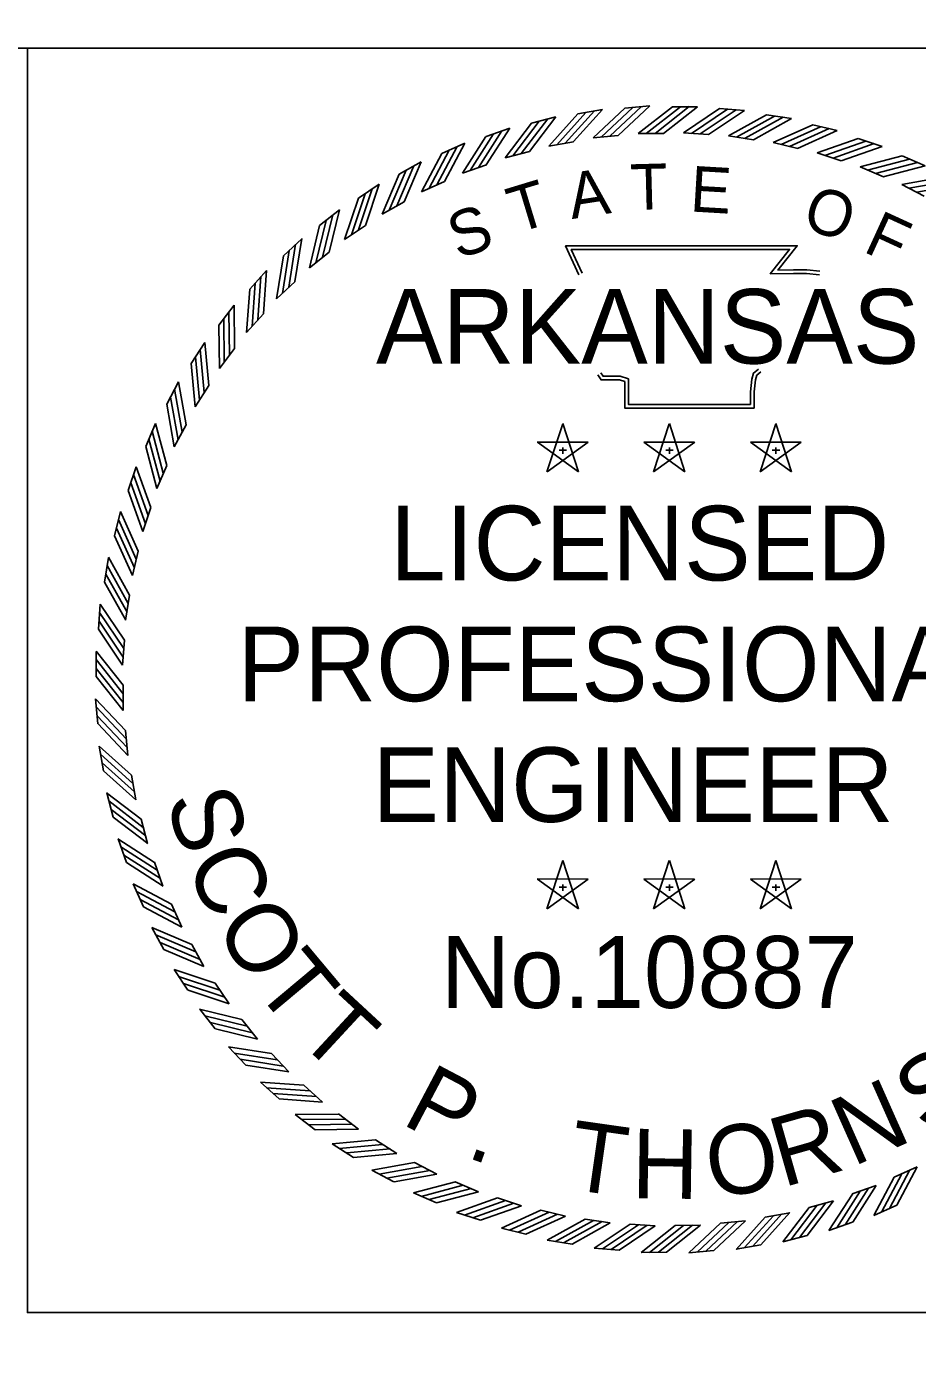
# Model space of a CAD drawing. Extents: x 0 to 1228740, y 0 to 152440.
# Drawn here: x 30.665 to 32.593, y 17.304 to 20.19 of the extents above; entities that cross this region are included whole.
import ezdxf

# ---------------------------------------------------------------- set-up
doc = ezdxf.new("R2010")
doc.units = 0
for name, color, linetype in [('R_Border', 7, 'Continuous'), ('R_No Plot', 7, 'Continuous'), ('STAMP_PP', 7, 'Continuous')]:
    doc.layers.add(name, color=color, linetype=linetype)

msp = doc.modelspace()

# ---------------------------------------------------------------- linework, layer by layer
at = {"layer": 'R_Border'}
msp.add_line((29.1131, 20.1432), (33.4231, 20.1432), dxfattribs=at)
at = {"layer": 'R_No Plot'}
for points in [[(33.4231, 17.4052), (33.4231, 0.5768), (1.516, 0.5768), (1.516, 21.4232), (20.2672, 21.4232), (20.2672, 20.4352), (28.7566, 20.4351), (28.7566, 20.0873), (29.1132, 20.0873), (29.1131, 20.1432), (30.6665, 20.1432)], [(30.6665, 20.1432), (30.6665, 17.4052), (33.4231, 17.4052)]]:
    msp.add_lwpolyline(points, dxfattribs=at)
msp.add_lwpolyline([(20.2672, 21.4232), (1.516, 21.4232), (1.516, 10.8708), (33.4231, 10.8708), (33.4231, 17.4052), (30.6665, 17.4052), (30.6665, 20.1432), (29.1132, 20.1432), (29.1132, 20.0873), (28.7566, 20.0873), (28.7566, 20.4351), (20.2672, 20.4351)], close=True, dxfattribs=at)
at = {"layer": 'STAMP_PP'}
for p, q in [((31.8584, 20.0015), (31.912, 20.0109)), ((31.9602, 20.0137), (32.0144, 20.0186)), ((32.0633, 20.0167), (32.1177, 20.0167)), ((32.1652, 20.0126), (32.2194, 20.0086)), ((31.7579, 19.981), (31.8105, 19.9948)), ((32.2669, 19.9994), (32.3206, 19.9909)), ((32.3671, 19.9778), (32.42, 19.965)), ((31.6595, 19.9522), (31.7108, 19.9703)), ((31.8916, 19.9492), (31.9459, 19.9542)), ((31.989, 19.9588), (32.0435, 19.9588)), ((32.0869, 19.9603), (32.1413, 19.9563)), ((32.1845, 19.9538), (32.2384, 19.9453)), ((32.4653, 19.9481), (32.5169, 19.9309)), ((31.5637, 19.9154), (31.6134, 19.9377)), ((31.7008, 19.9061), (31.7536, 19.9199)), ((31.7953, 19.9316), (31.849, 19.941)), ((32.2813, 19.9392), (32.3343, 19.9263)), ((32.3766, 19.9166), (32.4283, 19.8994)), ((31.4714, 19.8708), (31.519, 19.8972)), ((31.6088, 19.8729), (31.6602, 19.891)), ((32.5606, 19.9103), (32.6107, 19.8889)), ((32.4696, 19.8863), (32.5198, 19.8648)), ((31.383, 19.8188), (31.4283, 19.849)), ((31.5198, 19.8321), (31.5695, 19.8545)), ((32.5598, 19.8484), (32.608, 19.8229)), ((31.4344, 19.7842), (31.4821, 19.8106)), ((31.2992, 19.7596), (31.3419, 19.7934)), ((31.3533, 19.7294), (31.3987, 19.7597)), ((31.2206, 19.6937), (31.2603, 19.7309)), ((31.277, 19.6681), (31.3198, 19.702)), ((31.1477, 19.6216), (31.1842, 19.6619)), ((31.2061, 19.6007), (31.2459, 19.638)), ((31.0811, 19.5437), (31.1141, 19.5869)), ((31.1409, 19.5277), (31.1775, 19.5681)), ((31.021, 19.4605), (31.0504, 19.5063)), ((31.082, 19.4495), (31.1151, 19.4928)), ((30.9681, 19.3727), (30.9935, 19.4207)), ((31.0298, 19.3667), (31.0592, 19.4127)), ((30.9226, 19.2807), (30.944, 19.3308)), ((30.9845, 19.28), (31.01, 19.3281)), ((31.8255, 19.3302), (31.7915, 19.2258)), ((31.8594, 19.2258), (31.8256, 19.3303)), ((32.0563, 19.3302), (32.0222, 19.2258)), ((32.0902, 19.2258), (32.0564, 19.3303)), ((32.2871, 19.3302), (32.253, 19.2258)), ((32.321, 19.2258), (32.2871, 19.3303)), ((31.8804, 19.2904), (31.7705, 19.2905)), ((31.7706, 19.2904), (31.8594, 19.2257)), ((31.7916, 19.2258), (31.8805, 19.2903)), ((32.1112, 19.2904), (32.0013, 19.2905)), ((32.0014, 19.2904), (32.0902, 19.2257)), ((32.0224, 19.2258), (32.1113, 19.2903)), ((32.3419, 19.2904), (32.2321, 19.2905)), ((32.2322, 19.2904), (32.321, 19.2257)), ((32.2532, 19.2258), (32.3421, 19.2903)), ((31.8177, 19.2728), (31.834, 19.2728)), ((31.8256, 19.2787), (31.8256, 19.2649)), ((32.0485, 19.2728), (32.0648, 19.2728)), ((32.0564, 19.2787), (32.0564, 19.2649)), ((32.2793, 19.2728), (32.2956, 19.2728)), ((32.2872, 19.2787), (32.2872, 19.2649)), ((30.8848, 19.1854), (30.902, 19.237)), ((30.9466, 19.1897), (30.9681, 19.2399)), ((30.855, 19.0873), (30.8679, 19.1401)), ((30.9163, 19.0967), (30.9335, 19.1484)), ((30.8937, 19.0014), (30.9066, 19.0544)), ((30.8335, 18.987), (30.8419, 19.0407)), ((30.8203, 18.8853), (30.8243, 18.9395)), ((30.8791, 18.9046), (30.8876, 18.9585)), ((30.8726, 18.807), (30.8766, 18.8614)), ((30.8155, 18.7828), (30.815, 18.8372)), ((30.8741, 18.7091), (30.8736, 18.7637)), ((30.8192, 18.6803), (30.8142, 18.7345)), ((30.8837, 18.6117), (30.8787, 18.666)), ((30.8314, 18.5785), (30.822, 18.6321)), ((30.9013, 18.5154), (30.8918, 18.5691)), ((30.8519, 18.478), (30.8381, 18.5306)), ((30.9268, 18.4209), (30.9129, 18.4737)), ((30.8807, 18.3796), (30.8626, 18.4309)), ((30.96, 18.3289), (30.9419, 18.3803)), ((31.8255, 18.384), (31.7915, 18.2795)), ((31.8594, 18.2796), (31.8256, 18.3841)), ((32.0563, 18.384), (32.0222, 18.2795)), ((32.0902, 18.2796), (32.0564, 18.3841)), ((32.2871, 18.384), (32.253, 18.2795)), ((32.321, 18.2796), (32.2871, 18.3841)), ((30.9175, 18.2838), (30.8952, 18.3335)), ((31.8804, 18.3441), (31.7705, 18.3442)), ((31.7706, 18.3441), (31.8594, 18.2795)), ((31.7916, 18.2796), (31.8805, 18.3441)), ((31.8256, 18.3324), (31.8256, 18.3186)), ((32.1112, 18.3441), (32.0013, 18.3442)), ((32.0014, 18.3441), (32.0902, 18.2795)), ((32.0224, 18.2796), (32.1113, 18.3441)), ((32.0564, 18.3324), (32.0564, 18.3186)), ((32.3419, 18.3441), (32.2321, 18.3442)), ((32.2322, 18.3441), (32.321, 18.2795)), ((32.2532, 18.2796), (32.3421, 18.3441)), ((32.2872, 18.3324), (32.2872, 18.3186)), ((31.8177, 18.3266), (31.834, 18.3266)), ((32.0485, 18.3266), (32.0648, 18.3266)), ((32.2793, 18.3266), (32.2956, 18.3266)), ((31.0007, 18.2399), (30.9784, 18.2896)), ((30.9621, 18.1915), (30.9357, 18.2391)), ((31.0487, 18.1545), (31.0223, 18.2022)), ((31.0141, 18.1031), (30.9839, 18.1484)), ((31.1035, 18.0734), (31.0732, 18.1188)), ((31.0733, 18.0193), (31.0395, 18.062)), ((31.1648, 17.9971), (31.1309, 18.0399)), ((31.1392, 17.9407), (31.1019, 17.9804)), ((31.2322, 17.9262), (31.1949, 17.966)), ((31.2113, 17.8678), (31.1709, 17.9043)), ((31.3052, 17.861), (31.2648, 17.8976)), ((31.2892, 17.8012), (31.246, 17.8342)), ((31.3834, 17.8021), (31.34, 17.8352)), ((31.3724, 17.7411), (31.3266, 17.7705)), ((31.4661, 17.7499), (31.4202, 17.7793)), ((31.5529, 17.7046), (31.5047, 17.7301)), ((31.4602, 17.6882), (31.4121, 17.7136)), ((32.593, 17.7208), (32.5433, 17.6985)), ((31.6432, 17.6667), (31.593, 17.6882)), ((32.504, 17.6801), (32.4526, 17.662)), ((31.5521, 17.6427), (31.5021, 17.6641)), ((31.7362, 17.6364), (31.6845, 17.6536)), ((32.4119, 17.6469), (32.3592, 17.633)), ((32.549, 17.6376), (32.4994, 17.6153)), ((31.6475, 17.6049), (31.5959, 17.6221)), ((31.8315, 17.6138), (31.7785, 17.6267)), ((31.9283, 17.5992), (31.8744, 17.6077)), ((32.3175, 17.6214), (32.2637, 17.6119)), ((31.7456, 17.5751), (31.6928, 17.588)), ((32.0259, 17.5927), (31.9715, 17.5967)), ((32.1238, 17.5942), (32.0692, 17.5937)), ((32.2212, 17.6038), (32.1669, 17.5988)), ((32.4533, 17.6008), (32.402, 17.5827)), ((31.8459, 17.5536), (31.7922, 17.5621)), ((32.2544, 17.5515), (32.2008, 17.5421)), ((32.3549, 17.572), (32.3023, 17.5582)), ((31.9476, 17.5404), (31.8934, 17.5444)), ((32.0501, 17.5356), (31.9957, 17.5351)), ((32.1526, 17.5393), (32.0984, 17.5343))]:
    msp.add_line(p, q, dxfattribs=at)
for points in [[(31.8126, 19.9344), (31.8756, 20.0043)], [(31.8311, 19.9381), (31.8941, 20.008)], [(31.849, 19.9411), (31.912, 20.011)], [(31.8916, 19.9491), (31.9602, 20.0136)], [(31.909, 19.9506), (31.9776, 20.015)], [(31.9278, 19.9527), (31.9964, 20.0172)], [(31.9458, 19.9542), (32.0145, 20.0187)], [(31.9889, 19.9587), (32.0632, 20.0166)], [(32.0065, 19.9586), (32.0807, 20.0165)], [(32.0254, 19.959), (32.0996, 20.0169)], [(32.0435, 19.9588), (32.1177, 20.0167)], [(32.0868, 19.9603), (32.1651, 20.0126)], [(32.1043, 19.9588), (32.1825, 20.0111)], [(32.1231, 19.9579), (32.2014, 20.0101)], [(32.1412, 19.9564), (32.2195, 20.0087)], [(31.7008, 19.906), (31.7579, 19.9809)], [(31.7178, 19.9103), (31.7748, 19.9852)], [(31.7359, 19.9155), (31.793, 19.9904)], [(31.7535, 19.92), (31.8106, 19.9948)], [(31.7953, 19.9315), (31.8583, 20.0014)], [(32.1845, 19.9537), (32.2668, 19.9994)], [(32.2017, 19.9508), (32.2841, 19.9965)], [(32.2205, 19.9483), (32.3028, 19.994)], [(32.2383, 19.9453), (32.3207, 19.991)], [(32.2812, 19.9391), (32.3671, 19.9778)], [(32.2982, 19.9348), (32.384, 19.9735)], [(31.6087, 19.8728), (31.6594, 19.9521)], [(31.6253, 19.8785), (31.676, 19.9578)], [(31.643, 19.8852), (31.6937, 19.9645)], [(31.6601, 19.8911), (31.7108, 19.9704)], [(32.3167, 19.9308), (32.4025, 19.9695)], [(32.3342, 19.9263), (32.4201, 19.965)], [(32.3765, 19.9166), (32.4652, 19.9481)], [(31.5358, 19.8391), (31.5797, 19.9224)], [(31.5528, 19.8472), (31.5968, 19.9305)], [(31.5694, 19.8545), (31.6134, 19.9378)], [(32.393, 19.9109), (32.4818, 19.9424)], [(32.4111, 19.9053), (32.4998, 19.9368)], [(32.4282, 19.8994), (32.517, 19.9309)], [(31.4661, 19.802), (31.5031, 19.8886)], [(31.4821, 19.8106), (31.519, 19.8972)], [(31.5197, 19.8321), (31.5637, 19.9153)], [(32.4695, 19.8863), (32.5606, 19.9103)], [(32.4856, 19.8792), (32.5766, 19.9033)], [(32.5031, 19.8722), (32.5941, 19.8962)], [(32.5197, 19.8649), (32.6107, 19.8889)], [(31.4344, 19.7842), (31.4713, 19.8707)], [(31.4498, 19.7925), (31.4867, 19.8791)], [(32.5598, 19.8483), (32.6525, 19.8648)], [(31.3835, 19.7498), (31.4131, 19.8391)], [(31.3986, 19.7597), (31.4283, 19.849)], [(32.5752, 19.84), (32.6679, 19.8565)], [(32.5921, 19.8315), (32.6848, 19.848)], [(31.3533, 19.7293), (31.383, 19.8187)], [(31.368, 19.7389), (31.3976, 19.8283)], [(31.3054, 19.6909), (31.3276, 19.7823)], [(31.3197, 19.702), (31.3419, 19.7935)], [(31.277, 19.668), (31.2992, 19.7595)], [(31.2908, 19.6788), (31.313, 19.7703)], [(31.2324, 19.6257), (31.247, 19.7187)], [(31.2458, 19.638), (31.2603, 19.731)], [(31.8606, 19.6525), (31.8316, 19.7154), (32.3333, 19.7156), (32.2914, 19.663), (32.3255, 19.6634), (32.354, 19.6638), (32.3824, 19.6607)], [(31.2061, 19.6006), (31.2206, 19.6936)], [(31.2189, 19.6125), (31.2335, 19.7055)], [(31.8678, 19.6559), (31.844, 19.7074), (32.3169, 19.7077), (32.2748, 19.6548), (32.3256, 19.6555), (32.3536, 19.6558), (32.3816, 19.6528)], [(31.1774, 19.5681), (31.1842, 19.662)], [(31.1528, 19.5405), (31.1596, 19.6344)], [(31.1651, 19.5548), (31.172, 19.6487)], [(31.1409, 19.5276), (31.1477, 19.6215)], [(31.1039, 19.4785), (31.1029, 19.5727)], [(31.115, 19.4928), (31.1141, 19.587)], [(31.082, 19.4494), (31.0811, 19.5436)], [(31.0928, 19.4632), (31.0918, 19.5574)], [(31.0492, 19.3975), (31.0405, 19.4912)], [(31.0591, 19.4126), (31.0504, 19.5064)], [(31.0298, 19.3667), (31.021, 19.4604)], [(31.0393, 19.3813), (31.0306, 19.4751)], [(32.2543, 19.4423), (32.2457, 19.4353), (32.2429, 19.4249), (32.24, 19.3989), (32.24, 19.3642), (31.9599, 19.3642), (31.9599, 19.411), (31.9599, 19.4214), (31.9486, 19.4249), (31.9087, 19.4249), (31.9016, 19.4357)], [(32.2493, 19.4484), (32.2387, 19.4399), (32.235, 19.4264), (32.2321, 19.3993), (32.2321, 19.3721), (31.9679, 19.3721), (31.9679, 19.411), (31.9679, 19.4273), (31.9497, 19.4328), (31.913, 19.4328), (31.9083, 19.4401)], [(31.0013, 19.3122), (30.9849, 19.4049)], [(31.01, 19.3281), (30.9935, 19.4208)], [(30.9845, 19.2799), (30.9681, 19.3726)], [(30.9929, 19.2953), (30.9764, 19.388)], [(30.9607, 19.2232), (30.9367, 19.3142)], [(30.968, 19.2398), (30.944, 19.3308)], [(30.9466, 19.1896), (30.9226, 19.2807)], [(30.9537, 19.2057), (30.9296, 19.2967)], [(30.9335, 19.1484), (30.902, 19.2371)], [(30.922, 19.1131), (30.8905, 19.2019)], [(30.9276, 19.1312), (30.8961, 19.2199)], [(30.9163, 19.0966), (30.8848, 19.1853)], [(30.9066, 19.0544), (30.8679, 19.1402)], [(30.9021, 19.0368), (30.8634, 19.1226)], [(30.8938, 19.0013), (30.8551, 19.0872)], [(30.8981, 19.0183), (30.8594, 19.1041)], [(30.8846, 18.9406), (30.8389, 19.0229)], [(30.8876, 18.9585), (30.8419, 19.0408)], [(30.8821, 18.9218), (30.8364, 19.0042)], [(30.8792, 18.9046), (30.8335, 18.9869)], [(30.8765, 18.8613), (30.8242, 18.9396)], [(30.875, 18.8432), (30.8227, 18.9215)], [(30.8726, 18.8069), (30.8203, 18.8852)], [(30.8741, 18.8244), (30.8218, 18.9026)], [(30.8736, 18.7636), (30.815, 18.8373)], [(30.8736, 18.7455), (30.815, 18.8192)], [(30.8741, 18.7266), (30.8156, 18.8003)], [(30.8741, 18.7091), (30.8156, 18.7828)], [(30.8787, 18.666), (30.8142, 18.7346)], [(30.8802, 18.6479), (30.8157, 18.7165)], [(30.8823, 18.6291), (30.8178, 18.6977)], [(30.8838, 18.6117), (30.8193, 18.6803)], [(30.8918, 18.5691), (30.8219, 18.6321)], [(30.8948, 18.5512), (30.8249, 18.6142)], [(30.8985, 18.5327), (30.8286, 18.5957)], [(30.9014, 18.5154), (30.8315, 18.5784)], [(30.9129, 18.4736), (30.838, 18.5307)], [(30.9174, 18.456), (30.8425, 18.5131)], [(30.9226, 18.4379), (30.8477, 18.4949)], [(30.9269, 18.4209), (30.852, 18.478)], [(30.9418, 18.3802), (30.8625, 18.4309)], [(30.9477, 18.3631), (30.8684, 18.4138)], [(30.9544, 18.3454), (30.8751, 18.3961)], [(30.9601, 18.3288), (30.8808, 18.3795)], [(30.9784, 18.2895), (30.8951, 18.3335)], [(30.9857, 18.2729), (30.9024, 18.3169)], [(30.9938, 18.2559), (30.9105, 18.2998)], [(31.0008, 18.2398), (30.9176, 18.2838)], [(31.0223, 18.2022), (30.9357, 18.2391)], [(31.0309, 18.1862), (30.9443, 18.2232)], [(31.0404, 18.1699), (30.9538, 18.2068)], [(31.0487, 18.1545), (30.9621, 18.1914)], [(31.0732, 18.1187), (30.9839, 18.1484)], [(31.0831, 18.1036), (30.9938, 18.1332)], [(31.094, 18.0881), (31.0046, 18.1177)], [(31.1035, 18.0734), (31.0142, 18.1031)], [(31.1309, 18.0398), (31.0394, 18.062)], [(31.142, 18.0255), (31.0505, 18.0477)], [(31.1541, 18.0109), (31.0626, 18.0331)], [(31.1649, 17.9971), (31.0734, 18.0193)], [(31.1949, 17.9659), (31.1019, 17.9804)], [(31.2072, 17.9526), (31.1142, 17.9671)], [(31.2204, 17.939), (31.1274, 17.9536)], [(31.2323, 17.9262), (31.1393, 17.9407)], [(31.2648, 17.8975), (31.1709, 17.9043)], [(31.2781, 17.8852), (31.1842, 17.8921)], [(31.2924, 17.8729), (31.1985, 17.8797)], [(31.3053, 17.861), (31.2114, 17.8678)], [(31.3401, 17.8351), (31.2459, 17.8342)], [(31.3544, 17.824), (31.2602, 17.8231)], [(31.3696, 17.8129), (31.2755, 17.8119)], [(31.3835, 17.8021), (31.2893, 17.8012)], [(31.4203, 17.7792), (31.3265, 17.7705)], [(31.4354, 17.7693), (31.3417, 17.7606)], [(31.4516, 17.7595), (31.3578, 17.7507)], [(31.4662, 17.7499), (31.3725, 17.7411)], [(31.5048, 17.7301), (31.4121, 17.7136)], [(31.5207, 17.7215), (31.428, 17.705)], [(31.5376, 17.713), (31.4449, 17.6965)], [(31.553, 17.7046), (31.4603, 17.6882)], [(32.5434, 17.6985), (32.4994, 17.6152)], [(32.56, 17.7058), (32.516, 17.6225)], [(32.577, 17.7139), (32.5331, 17.6306)], [(32.5931, 17.7209), (32.5491, 17.6377)], [(31.5931, 17.6881), (31.5021, 17.6641)], [(31.6097, 17.6808), (31.5187, 17.6568)], [(31.6272, 17.6738), (31.5362, 17.6497)], [(31.6433, 17.6667), (31.5522, 17.6427)], [(32.4698, 17.6678), (32.4191, 17.5885)], [(32.4875, 17.6745), (32.4368, 17.5952)], [(32.5041, 17.6802), (32.4534, 17.6009)], [(31.6845, 17.6536), (31.5958, 17.6221)], [(31.7017, 17.6477), (31.613, 17.6162)], [(31.7197, 17.6421), (31.631, 17.6106)], [(31.7363, 17.6364), (31.6476, 17.6049)], [(32.3768, 17.6375), (32.3198, 17.5626)], [(32.395, 17.6427), (32.338, 17.5678)], [(32.412, 17.647), (32.3549, 17.5721)], [(32.4527, 17.6619), (32.402, 17.5826)], [(31.7785, 17.6267), (31.6927, 17.588)], [(31.7961, 17.6222), (31.7103, 17.5835)], [(31.8146, 17.6182), (31.7288, 17.5795)], [(31.8315, 17.6139), (31.7457, 17.5752)], [(31.8744, 17.6077), (31.7921, 17.562)], [(32.2638, 17.6119), (32.2008, 17.542)], [(32.2817, 17.6149), (32.2186, 17.545)], [(32.3002, 17.6186), (32.2372, 17.5487)], [(32.3175, 17.6215), (32.2545, 17.5516)], [(32.3593, 17.633), (32.3022, 17.5581)], [(31.8923, 17.6047), (31.81, 17.559)], [(31.9111, 17.6022), (31.8287, 17.5565)], [(31.9283, 17.5993), (31.846, 17.5536)], [(31.9716, 17.5966), (31.8933, 17.5443)], [(31.9896, 17.5951), (31.9114, 17.5428)], [(32.0085, 17.5942), (31.9302, 17.5419)], [(32.026, 17.5927), (31.9477, 17.5404)], [(32.0693, 17.5937), (31.9956, 17.5351)], [(32.0874, 17.5937), (32.0137, 17.5351)], [(32.1063, 17.5943), (32.0326, 17.5357)], [(32.1238, 17.5943), (32.0501, 17.5357)], [(32.1669, 17.5988), (32.0983, 17.5343)], [(32.185, 17.6003), (32.1164, 17.5358)], [(32.2038, 17.6024), (32.1352, 17.538)], [(32.2212, 17.6039), (32.1526, 17.5394)]]:
    msp.add_lwpolyline(points, dxfattribs=at)

# ---------------------------------------------------------------- texts
for s, height, rotation, p in [('T', 0.099, 1.4789, (31.9731, 19.793)), ('E', 0.099, 356.672, (32.0998, 19.79)), ('T', 0.099, 16.9015, (31.7251, 19.742)), ('A', 0.099, 8.6788, (31.8453, 19.7733)), ('O', 0.099, 341.2218, (32.3401, 19.7561)), ('S', 0.099, 19.7726, (31.5992, 19.6855)), ('F', 0.099, 335.3628, (32.4735, 19.7039)), ('S', 0.1503, 286.9475, (30.9653, 18.5171)), ('C', 0.1503, 294.2435, (31.0071, 18.3799)), ('O', 0.1503, 301.9044, (31.0694, 18.2429)), ('T', 0.1503, 309.93, (31.1536, 18.1096)), ('T', 0.1503, 317.226, (31.2456, 17.9997)), ('S', 0.1503, 32.7397, (32.6095, 17.7919)), ('P', 0.1503, 332.1828, (31.4737, 17.8153)), ('N', 0.1503, 23.9845, (32.4533, 17.72)), ('R', 0.1503, 15.9589, (32.302, 17.6757)), ('T', 0.1503, 351.882, (31.832, 17.6734)), ('O', 0.1503, 7.9332, (32.146, 17.6529)), ('H', 0.1503, 359.178, (31.974, 17.6531)), ('.', 0.1503, 340.2084, (31.6136, 17.7427))]:
    msp.add_text(s, height=height, rotation=rotation, dxfattribs=at).set_placement(p)
for s, height, p in [('ARKANSAS', 0.16155, (31.4214, 19.4603)), ('LICENSED', 0.16155, (31.4521, 18.9908)), ('PROFESSIONAL', 0.161547, (31.1214, 18.7292)), ('ENGINEER', 0.16155, (31.4137, 18.4677)), ('No.10887', 0.15578, (31.5614, 18.0649))]:
    msp.add_text(s, height=height, dxfattribs=at).set_placement(p)

doc.saveas('drawing.dxf')
